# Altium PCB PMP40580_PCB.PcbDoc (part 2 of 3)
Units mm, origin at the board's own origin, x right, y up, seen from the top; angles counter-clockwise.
Board outline 215 x 165 mm, 2 copper layers (Top Layer, Bottom Layer), stack 1.575 mm thick; 235 components, 90 nets, 527 pads, 0 vias.
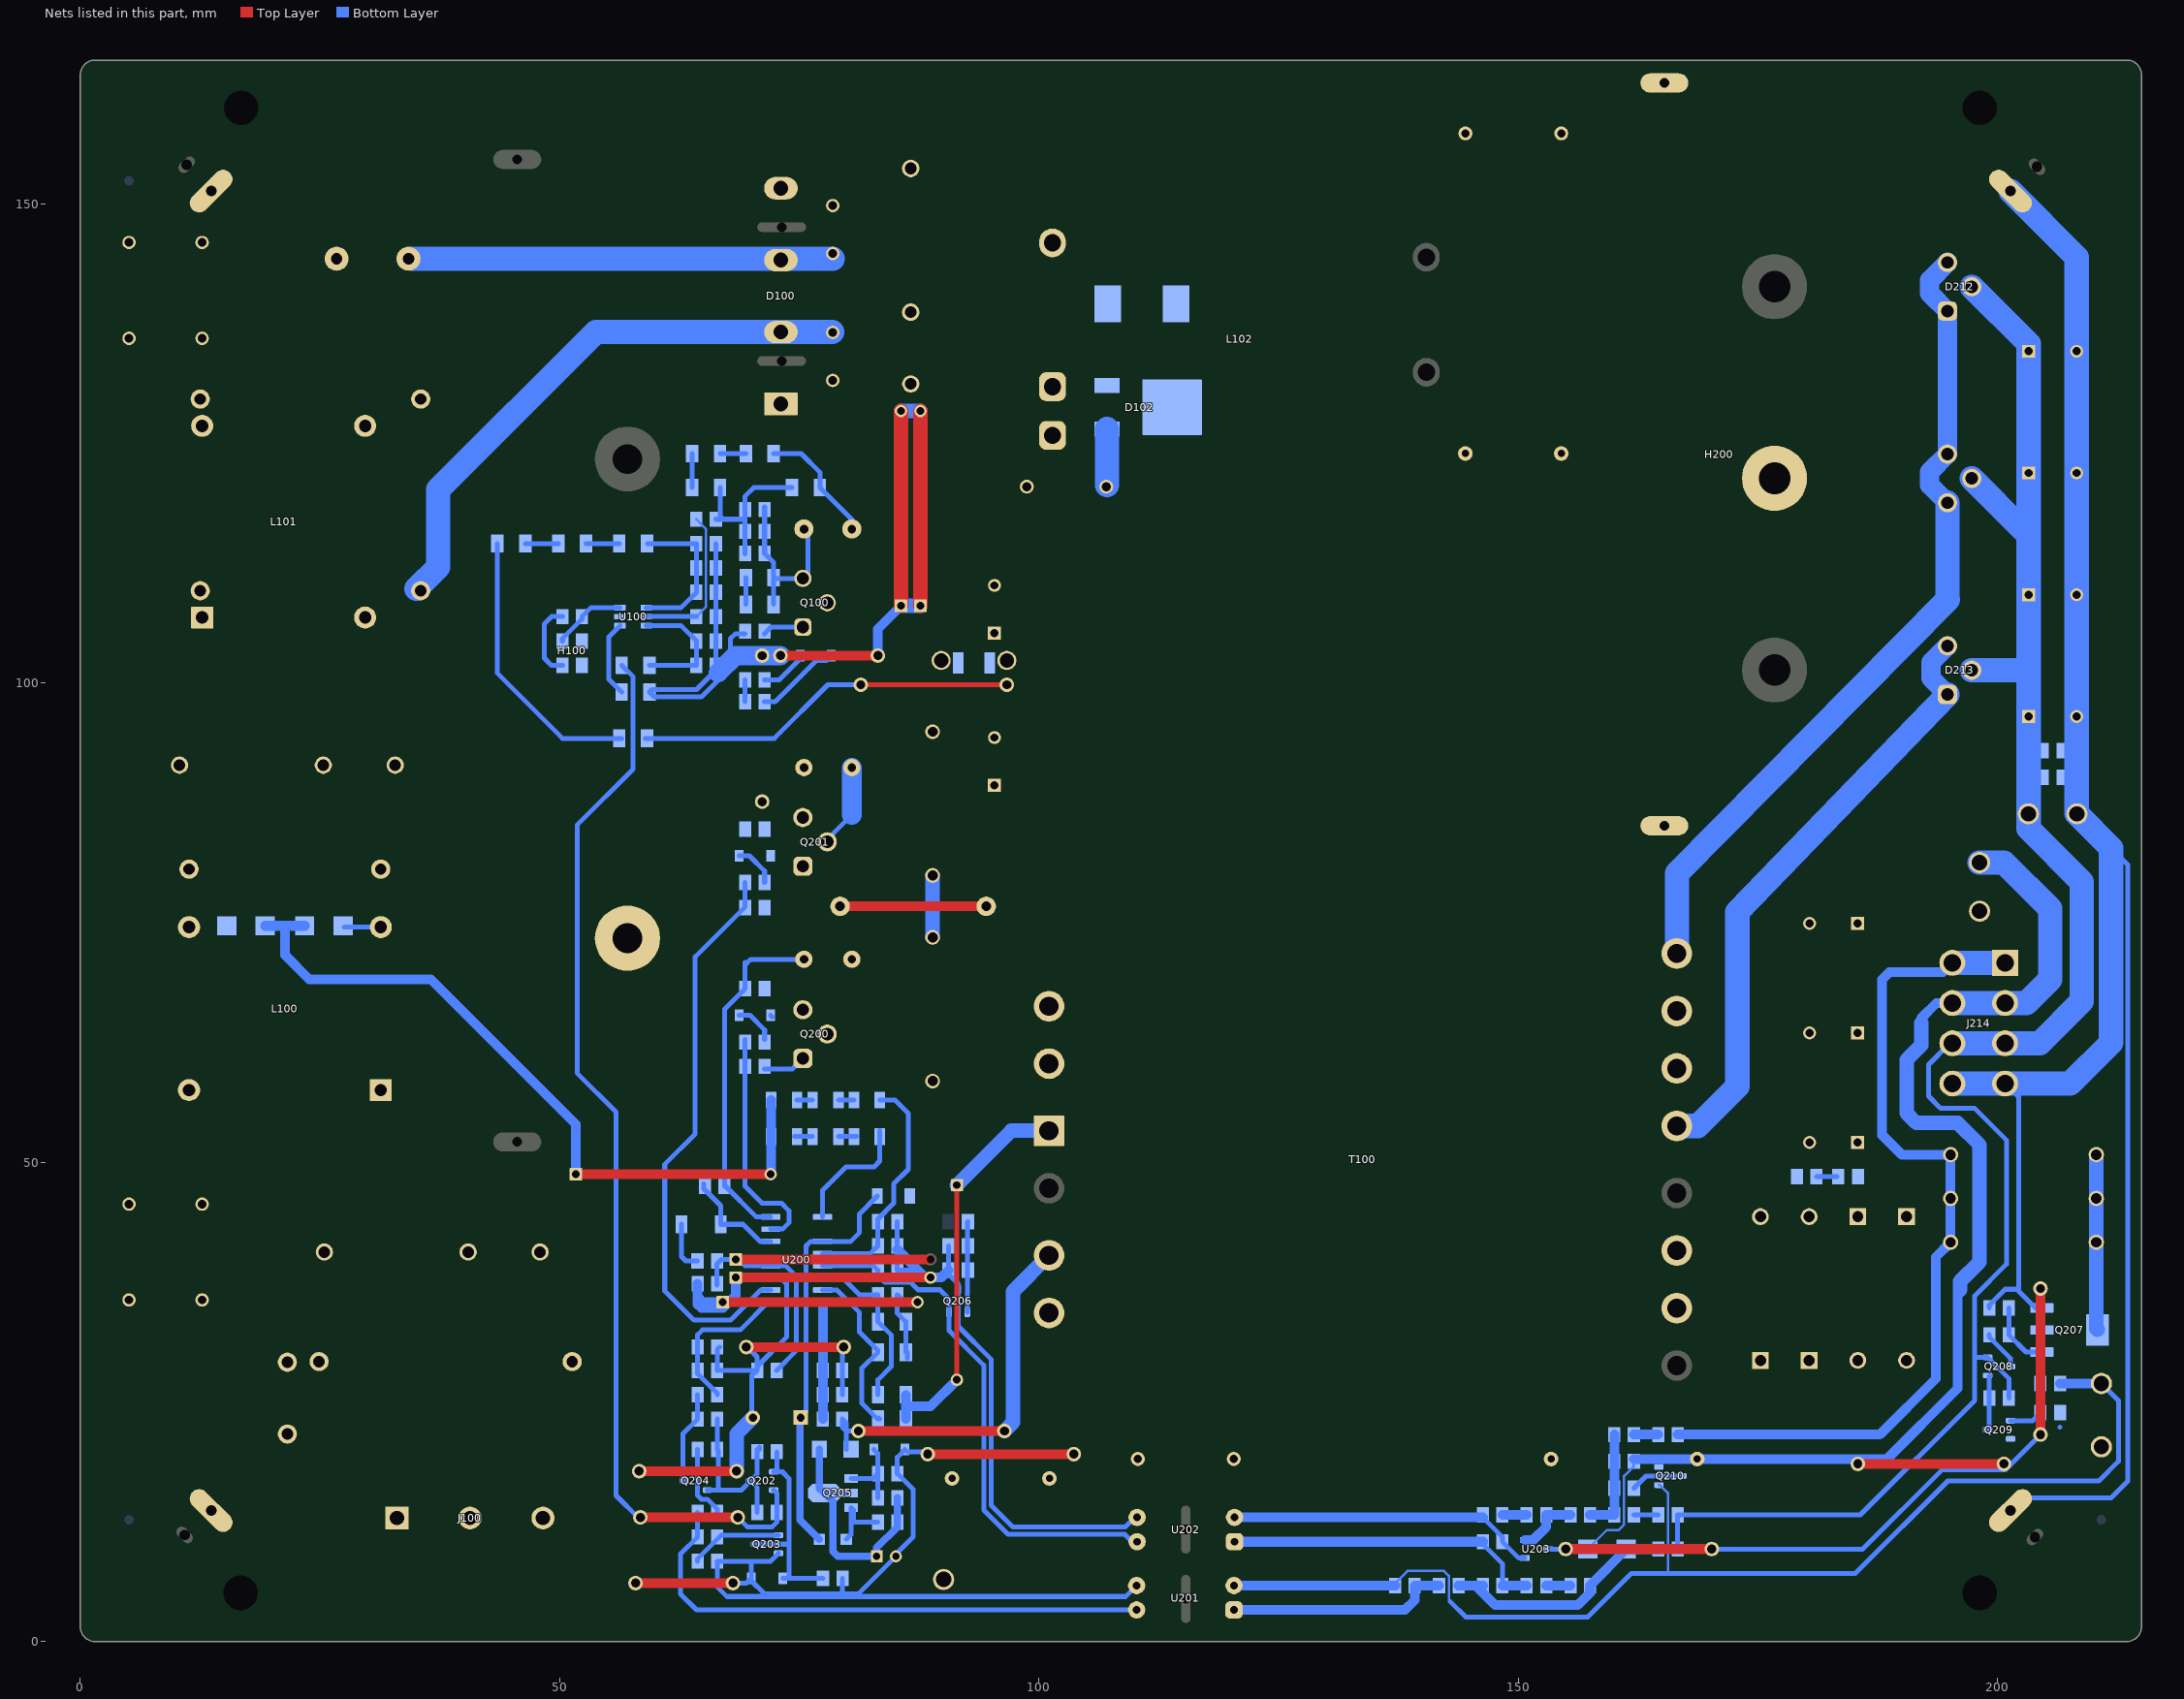
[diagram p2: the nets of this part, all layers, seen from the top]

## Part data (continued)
C217: "CAP, CERM, 10 pF, 50 V,+/- 5%, C0G/NP0, 0805", Cap_Case=0805, Manufacturer=Kemet, Supplier Part Number 1=399-1108-1-ND, TempCo=C0G/NP0, Tolerance_%=5, Value1="0.285 ohm", Value2=50V, ValueDisplayed=10pF
C218: "CAP, CERM, 2.2 µF, 16 V,+/- 10%, X7R, 0805", Cap_Case=0805, Manufacturer=MuRata, TempCo=X7R, Tolerance_%=10, Value2=16V, ValueDisplayed=2.2µF
C219 C221: "CAP, CERM, 470 pF, 25 V,+/- 10%, X7R, 0805", Cap_Case=0805, Manufacturer=MuRata, Supplier Part Number 1=GRM216R71E471KA01D-ND, TempCo=X7R, Tolerance_%=10, Value2=25V, ValueDisplayed=470pF
C220: "CAP, CERM, 0.1 µF, 25 V,+/- 10%, X7R, 0805", Cap_Case=0805, Manufacturer=Kemet, Supplier Part Number 1=399-1168-1-ND, TempCo=X7R, Tolerance_%=10, Value1="0.064 ohm", Value2=25V, ValueDisplayed=0.1µF
C222 C223 C224: "CAP, AL, 6.8 µF, 400 V, +/- 20%, TH", Cap_Case=10x16mm, Manufacturer=Chemi-Con, Supplier Part Number 1=565-1460-ND, Tolerance_%=20, Value2=400V, ValueDisplayed=6.8µF
C225 C226 C227 C228: "CAP, AL, 470 µF, 25 V, +/- 20%, AEC-Q200 Grade 2, TH", Cap_Case=10x16mm, Manufacturer=Chemi-Con, Supplier Part Number 1=565-1958-ND, Tolerance_%=20, Value2=25V, ValueDisplayed=470µF
C229: "CAP, CERM, 10 µF, 25 V,+/- 10%, X7S, 0805", Cap_Case=0805, Manufacturer=MuRata, Supplier Part Number 1=490-10496-1-ND, TempCo=X7S, Tolerance_%=10, Value2=25V, ValueDisplayed=10µF
C230: "CAP, CERM, 0.1 µF, 25 V,+/- 10%, X7R, 0805", Cap_Case=0805, Manufacturer=MuRata, Supplier Part Number 1=490-1673-1-ND, TempCo=X7R, Tolerance_%=10, Value2=25V, ValueDisplayed=0.1µF
C231: "CAP, CERM, 3300 pF, 50 V,+/- 10%, X7R, 0805", Cap_Case=0805, Manufacturer=AVX, Supplier Part Number 1=478-1377-1-ND, TempCo=X7R, Tolerance_%=10, Value1="0.145 ohm", Value2=50V, ValueDisplayed=3300pF
C232: "CAP, CERM, 0.01 µF, 100 V,+/- 10%, X7R, 0805", Cap_Case=0805, Manufacturer=Kemet, Supplier Part Number 1=399-1159-1-ND, TempCo=X7R, Tolerance_%=10, Value1="1.739 ohm", Value2=100V, ValueDisplayed=0.01µF
C233 C234: library part DE1E3KX102MA5BA01, "CAP, CERM, 470 pF, 250 V, +/- 20%, E, Disc, 8x12mm", Cap_Case=DE_800x1200x800, Manufacturer=MuRata, TempCo=E, Tolerance_%=20, Value1=Unknown, Value2=250V, ValueDisplayed=470pF
D100: library part GBU4J-BP, "Diode, P-N-Bridge, 600 V, 15 A, TH", Manufacturer="Taiwan Semiconductor Corporation", Value1=15A, Value2=1V
D101: "Diode, Ultrafast, 600 V, 3 A, SMC", Manufacturer="ON Semiconductor", Supplier Part Number 1=MURS360T3GOSCT-ND, Value1=3A, Value2=1.25V
D102: library part CMP-0077041-3, "Diode, Ultrafast, 600 V, 5 A, DPAK", Manufacturer="ON Semiconductor", Value1=5A, Value2=2.7V
D103 D201 D202: "Diode, Ultrafast, 100 V, 0.15 A, SOD-123", Manufacturer="Diodes Inc.", Supplier Part Number 1=1N4148W-FDICT-ND, Value1=0.15A, Value2=1.25V
D104 D105: "Diode, Ultrafast, 600 V, 1 A, AEC-Q101, SMA", Manufacturer="ON Semiconductor", Supplier Part Number 1=MURA160T3GOSCT-ND, Value1=1A, Value2=1.05V
D203: "Diode, Schottky, 100 V, 2 A, AEC-Q101, SOD-123W", Manufacturer=Nexperia, Supplier Part Number 1=568-12695-1-ND, Value1=2A, Value2=0.83V
D204: "Diode, Zener, 12 V, 500 mW, SOD-123", Manufacturer="ON Semiconductor", Power_W=0.5, Supplier Part Number 1=MMSZ4699T1GOSCT-ND, Value1=0.5W
D205: "Diode, Schottky, 60 V, 1 A, SOD-123F", Manufacturer=Nexperia, Supplier Part Number 1=568-4104-1-ND, Value1=1A, Value2=0.57V
D206: "Diode, Zener, 15 V, 370 mW, AEC-Q101, SOD-123", Manufacturer="Diodes Inc.", Power_W=0.37, Supplier Part Number 1=BZT52C15-FDICT-ND, Value1=0.37W
D207: library part CMP-0029162-1, "Diode, Ultrafast, 600 V, 1 A, AEC-Q101, SMAF", Manufacturer="Fairchild Semiconductor", Supplier Part Number 1=ES1JAFCT-ND, Value1=1A, Value2=1.7V
D208 D209 D210 D211: "Diode, Ultrafast, 200 V, 1.5 A, TH", Manufacturer=STMicroelectronics, Supplier Part Number 1=497-5571-3-ND, Value1=1.5A, Value2=1V
D212 D213: "Diode, Schottky, 45 V, 20 A, TH", Manufacturer=STMicroelectronics, Supplier Part Number 1=497-7567-5-ND, Value1=20A, Value2=0.49V
D214: library part CMP-0005522-2, "Diode, Zener, 11 V, 1.5 W, SMA", Manufacturer="ON Semiconductor", Power_W=1.5W, Supplier Part Number 1=45W9639
F100: "Fuse, 3.15 A, 250 VAC, TH", Irating_A=3.15A, Manufacturer=Littelfuse, Supplier Part Number 1=F3478-ND
FID1 FID2 FID3: library part CMP-0077181-1, "Fiducial mark.  There is nothing to buy or mount.", Manufacturer=N/A
H1 H2 H3 H4: "Standoff, Hex, 1\"L #6-32 Nylon, M-F", Manufacturer=Keystone, Supplier Part Number 1=36-4820-ND
H5 H6 H7 H8: library part CMP-0003679-1, Manufacturer=Keystone, Supplier Part Number 1=36-1903C-ND
H9 H10 H11 H12: library part 108-0740-001, "GND connector"
H13 H14 H15 H16: "MACHINE SCREW PAN PHILLIPS M3 5mm", Manufacturer="B&F Fastener Supply", Supplier Part Number 1=H742-ND
H17 H18 H19: "MACHINE SCREW PAN PHILLIPS M3", Manufacturer="APM HEXSEAL", Supplier Part Number 1=335-1149-ND
H20 H21 H22: "Hex Nuts: M3 X .5MM pitch DIN 934 A2 - 304 Stainless", Manufacturer="InStock Fasteners"
H100: library part HeatSink_2840x500x600_PQFP64-PBH, "Extruded Heatsink, 100mm, CUSTOM", Manufacturer="Texas Instruments"
H200: library part HeatSink_2840x500x600_PQFP64-PBH, "Extruded Heatsink, 75mm, CUSTOM", Manufacturer="Texas Instruments"
J100: library part 691312410003, "Serie 3124 - 7.62mm Open Horizontal PCB Header WR-TBL, 3 pin", Operating Temperature="-40 to 105 degC"
J101 J102 J103 J202 J206 J209 J210: library part CMP-0086939-1, Manufacturer=3M
J104 J106 J201 J203 J204 J211 J212 J213: "Jumper Wire, 600mil spacing, Blue, pkg of 150, TH", Manufacturer=3M, Supplier Part Number 1=923345-06-ND
J105 J200 J205 J207 J208: "Jumper Wire, 400 mil Spacing, Yellow, Pkg of 200", Manufacturer=3M, Supplier Part Number 1=923345-04-ND
J214: "THT Male Header WR-MPC4, Right Angled, Dual Row, pitch 4.2 mm, 8 pins", Contact Resistance="10 mOhm", Operating Temperature="-40 to 105 degC", Working Voltage="600 VAC"
L100 L101: library part "PMP40348 CM", "Coupled inductor, 20 mH, 3 A, 0.16 ohm, TH", Manufacturer=Jewel, ValueDisplayed=20mH
L102: library part BK-35, "Inductor, 200 µH, 0.235 ohm, TH", Manufacturer=Jewel, Value1="0.235 ohm", Value2=A
L103: "Ferrite Bead, 75 ohm @ 100 MHz, 5 A, D3.51xL4.45mm", Manufacturer="Laird-Signal Integrity Products", Supplier Part Number 1=240-2438-1-ND, Value1="0.01 ohm", Value2=5A, ValueDisplayed="75 ohm"
Logo1: library part CMP-0074835-1, "IEC 61010-1 High Voltage Warning"
Logo2: library part CMP-0074837-1, "IEC 61010-1 Hot Surface Warning"
Logo3: library part CMP-0074847-1, "FCC_disclaimer"
Logo4: library part CMP-0074769-1
Q100: "MOSFET, N-CH, 600 V, 18 A, TO-220FP", Alternate Manufacturer=None, Manufacturer=STMicroelectronics, Supplier Part Number 1=497-15115-5-ND, Value1="? ohm", Value2="29 nC"
Q200 Q201: "MOSFET, N-CH, 650 V, 17.5 A, TO-220FP", Alternate Manufacturer=None, Manufacturer="Infineon Technologies", Supplier Part Number 1=IPA65R190CFD-ND, Value1="? ohm", Value2="68 nC"
Q202 Q203 Q209: library part "MMBT3904, Fairchild Semiconductor", "Transistor, NPN, 40 V, 0.2 A, SOT-23", Manufacturer="Fairchild Semiconductor", Supplier Part Number 1=MMBT3904FSCT-ND, Value1="0.2 A", Value2=300
Q204: library part "BC856B-7-F, Diodes Inc.", "Transistor, PNP, 65 V, 0.1 A, SOT-23", Manufacturer="Diodes Inc.", Supplier Part Number 1=BC856B-7FDICT-ND, Value1="0.1 A", Value2=330
Q205: library part "BCX56-16,115, Nexperia", "Transistor, NPN, 80 V, 1 A, AEC-Q101, SOT-89", Manufacturer=Nexperia, Supplier Part Number 1=568-1642-1-ND, Value1="1 A", Value2=250
Q206 Q208: library part "MMBT2907A, Fairchild Semiconductor", "Transistor, PNP, 60 V, 0.8 A, SOT-23", Manufacturer="Fairchild Semiconductor", Supplier Part Number 1=MMBT2907AFSCT-ND, Value1="0.8 A", Value2=300
Q207: "MOSFET, N-CH, 600 V, 0.3 A, SOT-223", Alternate Manufacturer=None, Manufacturer=STMicroelectronics, Supplier Part Number 1=497-3523-1-ND, Value1="? ohm", Value2="4.9 nC"
Q210: "MOSFET, N-CH, 60 V, 0.3 A, SOT-23", Alternate Manufacturer=None, Manufacturer=Vishay-Siliconix, Supplier Part Number 1=2N7002K-T1-E3CT-ND, Value1="4 ohm", Value2="0.4 nC"
R100: "VARISTOR 490V 1.2KA DISC 7MM", Manufacturer=Littelfuse, Supplier Part Number 1=F5397-ND
R102 R103 R104: library part CMP-0016708-3, "RES, 1.65 k, 1%, 0.25 W, AEC-Q200 Grade 0, 1206", Manufacturer=Vishay-Dale, Power_W=250mW, Supplier Part Number 1=541-1.65KFCT-ND, TempCo="100 ppm/C", Tolerance_%=1%, Value2=0.25W, Value_Code=1k65, ValueDisplayed=1.65k
R105: "Thermistor NTC, 4.70 ohm, 20%, 15x7mm", Manufacturer=TDK, Power_W=3.1, Supplier Part Number 1=495-2099-ND, Tolerance_%=20
R106: "RES, 51, 5%, 0.25 W, 1206", Manufacturer=Vishay-Dale, Power_W=0.25, Supplier Part Number 1=541-51ECT-ND, TempCo="200 ppm/C", Tolerance_%=5, Value1=5%, Value2=0.25W, Value_Code=51R0, ValueDisplayed=51
R107 R108 R109 R113 R114 R115: "RES, 3.32 M, 1%, 0.25 W, 1206", Manufacturer=Vishay-Dale, Power_W=0.25, Supplier Part Number 1=541-3.32MFCT-ND, TempCo="100 ppm/C", Tolerance_%=1, Value1=1%, Value2=0.25W, Value_Code=3M32, ValueDisplayed=3.32M
R110: "RES, 110 k, 1%, 0.125 W, 0805", Manufacturer=Vishay-Dale, Power_W=0.125, Supplier Part Number 1=541-110KCCT-ND, TempCo="100 ppm/C", Tolerance_%=1, Value1=1%, Value2=0.125W, Value_Code=110k
R111: "RES, 154 k, 1%, 0.125 W, 0805", Manufacturer=Vishay-Dale, Power_W=0.125, Supplier Part Number 1=541-154KCCT-ND, TempCo="100 ppm/C", Tolerance_%=1, Value1=1%, Value2=0.125W, Value_Code=154k
R112: "RES, 10.0, 1%, 0.25 W, 1206", Manufacturer=Vishay-Dale, Power_W=0.25, Supplier Part Number 1=541-10.0FCT-ND, TempCo="100 ppm/C", Tolerance_%=1, Value1=1%, Value2=0.25W, Value_Code=10R0, ValueDisplayed=10.0
R116: "RES, 24.9 k, 1%, 0.125 W, 0805", Manufacturer=Panasonic, Power_W=0.125, Supplier Part Number 1=P24.9KCCT-ND, TempCo="100 ppm/C", Tolerance_%=1, Value1=1%, Value2=0.125W, Value_Code=24k9, ValueDisplayed=24.9k
R117 R118: "RES, 0.12, 5%, 0.25 W, 1206", Manufacturer=Panasonic, Power_W=0.25, Supplier Part Number 1=P.12PCT-ND, TempCo="250 ppm/C", Tolerance_%=5, Value1=5%, Value2=0.25W, Value_Code=R120, ValueDisplayed=0.12
R119: "RES, 3.0 k, 5%, 0.125 W, 0805", Manufacturer=Vishay-Dale, Power_W=0.125, Supplier Part Number 1=541-3.0KACT-ND, TempCo="200 ppm/C", Tolerance_%=5, Value1=5%, Value2=0.125W, Value_Code=3k00, ValueDisplayed=3.0k
R120: "RES, 270 k, 5%, 0.125 W, 0805", Manufacturer=Vishay-Dale, Power_W=0.125, Supplier Part Number 1=541-270KACT-ND, TempCo="200 ppm/C", Tolerance_%=5, Value1=5%, Value2=0.125W, Value_Code=270k
R121 R200 R203: "RES, 47, 5%, 0.125 W, 0805", Manufacturer=Vishay-Dale, Power_W=0.125, Supplier Part Number 1=541-47ACT-ND, TempCo="200 ppm/C", Tolerance_%=5, Value1=5%, Value2=0.125W, Value_Code=47R0, ValueDisplayed=47
R122 R201 R204 R247: "RES, 22, 5%, 0.125 W, 0805", Manufacturer=Vishay-Dale, Power_W=0.125, Supplier Part Number 1=541-22ACT-ND, TempCo="200 ppm/C", Tolerance_%=5, Value1=5%, Value2=0.125W, Value_Code=22R0, ValueDisplayed=22
R123: "RES, 82.5 k, 1%, 0.125 W, 0805", Manufacturer=Vishay-Dale, Power_W=0.125, Supplier Part Number 1=541-82.5KCCT-ND, TempCo="100 ppm/C", Tolerance_%=1, Value1=1%, Value2=0.125W, Value_Code=82k5, ValueDisplayed=82.5k
R124: "RES, 0, 5%, 0.25 W, 1206", Manufacturer=Vishay-Dale, Power_W=0.25, Supplier Part Number 1=541-0.0ECT-ND, TempCo="200 ppm/C", Tolerance_%=5, Value1=5%, Value2=0.25W, Value_Code=0000, ValueDisplayed=0
R202 R205: "RES, 51 k, 5%, 0.125 W, 0805", Manufacturer=Vishay-Dale, Power_W=0.125, Supplier Part Number 1=541-51KACT-ND, TempCo="200 ppm/C", Tolerance_%=5, Value1=5%, Value2=0.125W, Value_Code=51k0, ValueDisplayed=51k
R207 R213 R215 R234: "RES, 0, 5%, 0.125 W, 0805", Manufacturer=Vishay-Dale, Power_W=0.125, Supplier Part Number 1=541-0.0ACT-ND, TempCo="200 ppm/C", Tolerance_%=5, Value1=5%, Value2=0.125W, Value_Code=0000, ValueDisplayed=0
R208 R214: "RES, 2.0 k, 5%, 0.125 W, 0805", Manufacturer=Vishay-Dale, Power_W=0.125, Supplier Part Number 1=541-2.0KACT-ND, TempCo="200 ppm/C", Tolerance_%=5, Value1=5%, Value2=0.125W, Value_Code=2k00, ValueDisplayed=2.0k
R209 R212 R227 R228 R229 R248 R249: "RES, 10 k, 5%, 0.125 W, 0805", Manufacturer=Vishay-Dale, Power_W=0.125, Supplier Part Number 1=541-10KACT-ND, TempCo="200 ppm/C", Tolerance_%=5, Value1=5%, Value2=0.125W, Value_Code=10k0, ValueDisplayed=10k
R210 R211 R226: "RES, 100 k, 5%, 0.125 W, 0805", Manufacturer=Vishay-Dale, Power_W=0.125, Supplier Part Number 1=541-100KACT-ND, TempCo="200 ppm/C", Tolerance_%=5, Value1=5%, Value2=0.125W, Value_Code=100k
R216: "RES, 866 k, 1%, 0.125 W, 0805", Manufacturer=Vishay-Dale, Power_W=0.125, Supplier Part Number 1=541-866KCCT-ND, TempCo="100 ppm/C", Tolerance_%=1, Value1=1%, Value2=0.125W, Value_Code=866k
R217: "RES, 750 k, 1%, 0.125 W, 0805", Manufacturer=Vishay-Dale, Power_W=0.125, Supplier Part Number 1=541-750KCCT-ND, TempCo="100 ppm/C", Tolerance_%=1, Value1=1%, Value2=0.125W, Value_Code=750k
R218: "RES, 133, 1%, 0.25 W, 1206", Manufacturer=Vishay-Dale, Power_W=0.25, Supplier Part Number 1=541-133FCT-ND, TempCo="100 ppm/C", Tolerance_%=1, Value1=1%, Value2=0.25W, Value_Code=133R, ValueDisplayed=133
R219: "RES, 2.2, 5%, 0.125 W, 0805", Manufacturer=Vishay-Dale, Power_W=0.125, Supplier Part Number 1=541-2.2ACT-ND, TempCo="200 ppm/C", Tolerance_%=5, Value1=5%, Value2=0.125W, Value_Code=2R20, ValueDisplayed=2.2
R220: "RES, 44.2 k, 1%, 0.125 W, 0805", Manufacturer=Vishay-Dale, Power_W=0.125, Supplier Part Number 1=541-44.2KCCT-ND, TempCo="100 ppm/C", Tolerance_%=1, Value1=1%, Value2=0.125W, Value_Code=44k2, ValueDisplayed=44.2k
R221: "RES, 8.06 k, 1%, 0.125 W, 0805", Manufacturer=Vishay-Dale, Power_W=0.125, Supplier Part Number 1=541-8.06KCCT-ND, TempCo="100 ppm/C", Tolerance_%=1, Value1=1%, Value2=0.125W, Value_Code=8k06, ValueDisplayed=8.06k
R222 R223 R224: library part CMP-0017039-3, "RES, 4.99 M, 1%, 0.25 W, AEC-Q200 Grade 0, 1206", Manufacturer=Vishay-Dale, Power_W=250mW, Supplier Part Number 1=541-4.99MFCT-ND, TempCo="100 ppm/C", Tolerance_%=1%, Value2=0.25W, Value_Code=4M99, ValueDisplayed=4.99M
R225: "RES, 300 k, 5%, 0.125 W, 0805", Manufacturer=Vishay-Dale, Power_W=0.125, Supplier Part Number 1=541-300KACT-ND, TempCo="200 ppm/C", Tolerance_%=5, Value1=5%, Value2=0.125W, Value_Code=300k
R230 R235: "RES, 3.01 k, 1%, 0.125 W, 0805", Manufacturer=Vishay-Dale, Power_W=0.125, Supplier Part Number 1=541-3.01KCCT-ND, TempCo="100 ppm/C", Tolerance_%=1, Value1=1%, Value2=0.125W, Value_Code=3k01, ValueDisplayed=3.01k
R231: "RES, 6.04 k, 1%, 0.125 W, 0805", Manufacturer=Vishay-Dale, Power_W=0.125, Supplier Part Number 1=541-6.04KCCT-ND, TempCo="100 ppm/C", Tolerance_%=1, Value1=1%, Value2=0.125W, Value_Code=6k04, ValueDisplayed=6.04k
R232: "RES, 330, 5%, 0.125 W, 0805", Manufacturer=Vishay-Dale, Power_W=0.125, Supplier Part Number 1=541-330ACT-ND, TempCo="200 ppm/C", Tolerance_%=5, Value1=5%, Value2=0.125W, Value_Code=330R, ValueDisplayed=330
R233: "RES, 33.2 k, 1%, 0.125 W, 0805", Manufacturer=Vishay-Dale, Power_W=0.125, Supplier Part Number 1=541-33.2KCCT-ND, TempCo="100 ppm/C", Tolerance_%=1, Value1=1%, Value2=0.125W, Value_Code=33k2, ValueDisplayed=33.2k
R236: "RES, 10, 5%, 0.125 W, 0805", Manufacturer=Vishay-Dale, Power_W=0.125, Supplier Part Number 1=541-10ACT-ND, TempCo="200 ppm/C", Tolerance_%=5, Value1=5%, Value2=0.125W, Value_Code=10R0, ValueDisplayed=10
R237: "RES, 147 k, 1%, 0.125 W, 0805", Manufacturer=Vishay-Dale, Power_W=0.125, Supplier Part Number 1=541-147KCCT-ND, TempCo="100 ppm/C", Tolerance_%=1, Value1=1%, Value2=0.125W, Value_Code=147k
R238 R239: "RES, 499 k, 1%, 0.125 W, 0805", Manufacturer=Vishay-Dale, Power_W=0.125, Supplier Part Number 1=541-499KCCT-ND, TempCo="100 ppm/C", Tolerance_%=1, Value1=1%, Value2=0.125W, Value_Code=499k
R240: "RES, 80.6 k, 1%, 0.125 W, 0805", Manufacturer=Vishay-Dale, Power_W=0.125, Supplier Part Number 1=541-80.6KCCT-ND, TempCo="100 ppm/C", Tolerance_%=1, Value1=1%, Value2=0.125W, Value_Code=80k6, ValueDisplayed=80.6k
R241: "RES, 21.5 k, 1%, 0.125 W, 0805", Manufacturer=Vishay-Dale, Power_W=0.125, Supplier Part Number 1=541-21.5KCCT-ND, TempCo="100 ppm/C", Tolerance_%=1, Value1=1%, Value2=0.125W, Value_Code=21k5, ValueDisplayed=21.5k
R242 R243: "RES, 3.3 M, 5%, 0.125 W, 0805", Manufacturer=Panasonic, Power_W=0.125, Supplier Part Number 1=P3.3MACT-ND, TempCo="150 ppm/C", Tolerance_%=5, Value1=5%, Value2=0.125W, Value_Code=3M30, ValueDisplayed=3.3M
R244 R245 R246: "RES, 100 k, 5%, 2 W, AEC-Q200 Grade 0, Axial resistor", Manufacturer=Vishay-Bccomponents, Power_W=2, Supplier Part Number 1=PPC100KW-2CT-ND, TempCo="250 ppm/C", Tolerance_%=5, Value1=5%, Value2=2W, Value_Code=100k
R250: "RES, 4.7 k, 5%, 0.125 W, 0805", Manufacturer=Vishay-Dale, Power_W=0.125, Supplier Part Number 1=541-4.7KACT-ND, TempCo="200 ppm/C", Tolerance_%=5, Value1=5%, Value2=0.125W, Value_Code=4k70, ValueDisplayed=4.7k
R251: "RES, 20 k, 5%, 0.125 W, 0805", Manufacturer=Vishay-Dale, Power_W=0.125, Supplier Part Number 1=541-20KACT-ND, TempCo="200 ppm/C", Tolerance_%=5, Value1=5%, Value2=0.125W, Value_Code=20k0, ValueDisplayed=20k
T100: library part EE42, "Transformer, 400uH, 14-pin, TH, EE49", Alternate Manufacturer=-, Manufacturer=Jewel
TP200 TP202 TP204 TP206: "Test Point, Multipurpose, Black, TH", Manufacturer=Keystone, Supplier Part Number 1=36-5011-ND
TP201 TP203 TP205: "Test Point, Multipurpose, Red, TH", Manufacturer=Keystone, Supplier Part Number 1=36-5010-ND
U100: "6-Pin Single-Phase Transition-Mode PFC Controller, DBV0006A (SOT-23-6)", Alternate Manufacturer="Texas Instruments"
U200: library part CMP-0077203-3, "Wide Vin LLC Resonant Controller With High-Voltage Start Up Enabling Low Standby Power, DDB0014A (SOIC-14)", Alternate Manufacturer="Texas Instruments", Alternate PartNumber=UCC25640-4DDBT, PartNumber=UCC25640-4DDBR
U201 U202: "Optocoupler, 5.3 kV, 50-600% CTR, TH", Manufacturer=Vishay-Semiconductor, Supplier Part Number 1=VO618A-ND, Voltage_Isolation_Vrms=5300V
U203: "Adjustable Precision Shunt Regulator, 34 ppm / degC, 100 mA, -40 to 85 degC, 3-pin SOT-23 (DBZ), Green (RoHS & no Sb/Br)", Alternate Manufacturer="Texas Instruments", Alternate PartNumber=Equivalent, Rating=Catalog, Supplier Part Number 1=296-17329-2-ND, Temp Coeff(Max)(ppm/ degree C)=92, Temp Coeff(Typ)(ppm/ degree C)=34

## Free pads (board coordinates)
  round 2 hole 1.2: 1(11.336,80.588) 1(12.503,109.634) 1(35.503,109.634) 1(35.503,129.634) 2(31.336,80.588) 3(12.503,129.634)
  round 2 hole 1.5: 1(89.789,102.362) 1(96.647,102.362)
  round 1.524 hole 0.762: 1(90.932,17.018) 1(144.479,123.952) 1(168.656,19.05) 2(101.092,17.018) 2(153.416,19.05) 2(154.479,123.952)
  round 2 hole 1.3: 1(194.767,118.811) 2(197.307,121.351) 3(194.767,123.891)
  round 1.8 hole 1.2: 2(25.34,91.44) 2(40.453,40.64) 2(86.626,138.712)
  oval 5.08x1 hole 1 slot 5.08 at 0 deg unplated: ""(73.152,133.604) ""(73.152,147.574)
  oval 1x5 hole 1 slot 5 at 90 deg unplated: ""(115.316,4.445) ""(115.316,11.684)

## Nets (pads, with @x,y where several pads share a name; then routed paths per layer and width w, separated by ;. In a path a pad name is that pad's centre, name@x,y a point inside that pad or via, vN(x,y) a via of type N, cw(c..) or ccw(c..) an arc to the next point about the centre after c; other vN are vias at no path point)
12V: C225.1 C226.1 C227.1 C228.1 C229.1 C230.1 D212.2 D213.2 J214.3 J214.7 pad.2@197.307,121.351 Q208.2 R235.2 R236.2 R249.2 TP203.1 | length 200
  Bottom Layer w0.508: R235.2@166.624,9.652 R236.2@166.624,13.208 185.674,13.208 197.612,25.146 197.612,29.652 ; J214.7@195.28,62.416 195.004,62.416 192.786,60.198 192.786,56.896 194.056,55.626 197.612,55.626 200.914,52.324 200.914,39.37 197.612,36.068 197.612,29.652 ; R249.2@201.168,25.4 201.168,27.436 Q208.2@198.952,29.652 197.612,29.652
  Bottom Layer w2.54: J214.7@195.28,62.416 J214.3@200.78,62.416 204.402,62.416 208.788,66.802 208.788,79.248 203.24,84.796 C228.1@203.24,96.52 203.24,101.346 ; D213.2@197.307,101.346 203.24,101.346 ; pad.2@197.307,121.351 202.58,116.078 203.24,116.078 ; D212.2@197.307,141.351 203.24,135.418 C225.1@203.24,134.62 C226.1@203.24,121.92 203.24,116.078 ; 203.24,101.346 C227.1@203.24,109.22 203.24,116.078
150V: C222.1 C223.1 C224.1 D208.1 D210.1 J214.1 J214.5 R238.2 R243.2 R244.2 R245.2 R246.2 TP201.1 | length 91.1
  Bottom Layer w1.016: R238.2@166.624,21.59 187.706,21.59 193.548,27.432 193.548,40.112 R246.2@195.092,41.656 R245.2@195.092,46.228 R244.2@195.092,50.8 189.992,50.8 187.96,52.832 187.96,67.31 187.96,69.088 188.722,69.85 194.314,69.85 J214.5@195.28,70.816
  Bottom Layer w2.54: J214.5@195.28,70.816 J214.1@200.78,70.816
ACIN: D104.1 D105.1 J101.1 J101.2 R104.2 R222.2 | length 78
  Top Layer w1.016: J101.1@51.689,48.768 J101.2@72.009,48.768
  Bottom Layer w1.016: D104.1@19.272,74.676 21.336,74.676 ; D105.1@23.4,74.676 21.336,74.676 ; J101.1@51.689,48.768 51.689,53.975 36.576,69.088 23.876,69.088 21.336,71.628 21.336,74.676 ; J101.2@72.009,48.768 J101.2@72.056,48.815 ; J101.2@72.056,48.688 J101.2@72.056,48.815 ; R104.2@72.056,52.435 J101.2@72.056,48.815 ; R104.2@72.056,52.689 R222.2@72.056,56.499
BLK: C220.1 R224.1 R225.2 U200.4 | length 24.8
  Bottom Layer w0.508: U200.4@77.423,40.487 82.397,40.487 C220.1@83.185,41.275 R225.2@83.185,43.815 83.185,44.069 84.836,45.72 84.836,47.752 86.36,49.276 86.36,55.118 84.979,56.499 R224.1@83.392,56.499
BW: C217.1 R220.1 R221.2 U200.8 | length 12
  Bottom Layer w0.508: U200.8@77.423,35.407 U200.8@77.45,35.379
  Bottom Layer w1.016: R220.1@77.45,23.21 C217.1@77.45,28.29 U200.8@77.45,35.179
COMP: C115.1 C116.1 U100.6 | length 7.7
  Bottom Layer w0.508: C116.1@50.292,104.394 50.292,104.648 52.324,106.68 C115.1@52.324,106.934 53.274,107.884 U100.6@56.283,107.884
DRV: R121.1 R122.1 U100.5 | length 2.3
  Bottom Layer w0.508: R121.1@69.342,98.044 R122.1@69.342,100.33
FB: C219.1 Q206.2 U200.5 U202.4 | length 55.8
  Bottom Layer w0.508: U200.5@77.423,39.217 82.703,39.217 C219.1@83.185,38.735 83.185,38.227 83.931,37.481 86.598,37.481 87.376,36.703 89.662,36.703 90.617,35.748 Q206.2@90.617,34.36 90.617,32.446 94.234,28.829 94.234,13.716 96.774,11.176 108.966,11.176 109.728,10.414 U202.4@110.236,10.414
HB: C218.1 D207.1 U200.14 | length 10.9
  Bottom Layer w0.508: C218.1@65.024,47.752 65.024,47.244 66.79,45.478 D207.1@66.79,43.53 69.119,43.53 70.892,41.757 U200.14@72.023,41.757
HO: R200.1 R201.1 U200.15 | length 24.1
  Bottom Layer w0.508: R200.1@69.342,59.754 69.342,47.498 71.12,45.72 73.152,45.72 73.914,44.958 73.914,43.688 73.253,43.027 U200.15@72.023,43.027 ; R200.1@69.342,60.008 R201.1@69.342,62.548 R201.1@69.342,62.802
HS: C201.1 C202.2 C218.2 J201.1 J201.2 Q200.3 Q201.2 R202.1 T100.5 T100.6 U200.16 | length 59.1
  Top Layer w1.016: J201.1@79.248,76.708 J201.2@94.368,76.708
  Bottom Layer w0.508: C218.2@67.198,47.498 67.198,65.991 R202.1@69.342,68.136 69.342,70.866 ; C218.2@67.31,47.498 70.511,44.297 U200.16@72.023,44.297 ; 69.342,70.612 69.914,71.184 C201.1@74.97,71.184 ; Q201.2@78.416,84.18 80.478,86.242
  Bottom Layer w2.032: 80.478,86.242 C202.2@80.478,91.186
HV: R102.1 U200.1 | length 13.2
  Bottom Layer w0.508: U200.1@77.423,44.297 77.423,47.07 79.883,49.53 82.804,49.53 83.392,50.118 R102.1@83.392,52.689 R102.1@83.392,53.324
ISNS: C205.2 C216.1 R218.2 U200.6 | length 18.1
  Bottom Layer w0.508: U200.6@77.423,37.947 79.502,37.947 81.254,36.195 C216.1@83.185,36.195 83.185,33.385 R218.2@83.2,33.37 84.582,31.988 84.582,28.691 83.2,27.309 C205.2@83.2,25.75
Line: F100.2 J100.3
LL: C213.1 R216.1 R217.2 U200.9 | length 16.1
  Bottom Layer w0.508: R216.1@66.421,25.75 66.421,25.908 64.389,27.94 R217.2@64.389,28.29 64.389,32.004 64.897,32.512 68.834,32.512 71.729,35.407 U200.9@72.023,35.407
LO: R203.1 R204.1 U200.10 | length 59.7
  Bottom Layer w0.508: R204.1@69.342,79.185 69.342,76.645 64.135,71.438 64.135,52.959 60.96,49.784 60.96,36.576 64.008,33.528 67.818,33.528 70.967,36.677 U200.10@72.023,36.677
NetC100_1: C100.1 C101.1 F100.1 L100.4 R100.2
NetC103_1: C103.1 C104.2 D104.2 L100.3 L101.4 pad.1@11.336,80.588 pad.3@12.503,129.634
NetC103_2: C103.2 C105.1 D105.2 L100.2 L101.1 pad.1@12.503,109.634 pad.2@25.34,91.44 pad.2@31.336,80.588 | length 2.8
  Bottom Layer w0.508: D105.2@27.536,74.54 L100.2@30.336,74.54
NetC106_2: C106.2 D100.3 R105.2 | length 43.8
  Bottom Layer w2.54: R105.2@34.655,144.272 C106.2@78.486,144.28
NetC107_1: C107.1 D100.2 L101.2 pad.1@35.503,109.634 | length 59.2
  Bottom Layer w2.54: pad.1@35.052,109.855 37.338,112.104 37.338,120.189 53.779,136.63 D100.2@73.076,136.63 C107.1@78.436,136.63
NetC107_2: C107.2 C108.1 D100.1 D101.2 L102.3
NetC111_1: C111.1 C114.2 L102.1 L102.2 L103.1 Q100.2 R113.2 | length 13
  Bottom Layer w0.508: R113.2@72.316,123.952 75.184,123.952 77.178,121.958 C111.1@77.178,120.36 ; C111.1@77.142,120.396 C111.1@77.178,120.36 ; C114.2@80.478,116.078 80.478,117.06 C111.1@77.178,120.36
NetC111_2: C111.2 C112.1 C113.1 R115.1 R116.2 R119.2 | length 21
  Bottom Layer w0.508: R119.2@66.294,117.094 67.056,117.094 ; R115.1@66.728,120.396 66.728,117.422 67.056,117.094 ; R116.2@69.342,113.48 R116.2@69.342,113.538 R116.2@69.342,114.3 ; C112.1@69.342,118.11 C112.1@69.342,118.618 ; C111.2@74.206,120.396 70.231,120.396 69.342,119.507 C112.1@69.342,118.618 ; 67.056,117.094 69.342,117.094 ; R116.2@69.342,114.3 C113.1@69.342,115.824 69.342,117.094 ; R116.2@69.342,114.3 69.342,117.094 ; 69.342,117.094 C112.1@69.342,118.618
NetC112_2: C112.2 C113.2 C114.1 Q100.3 R116.1 R117.2 R118.2 | length 19.3
  Bottom Layer w0.508: C112.2@71.374,118.364 71.374,116.078 R116.1@71.374,113.538 72.316,112.596 R118.2@72.316,110.998 ; R117.2@72.316,108.204 72.316,110.842 72.394,110.92 75.876,110.92 75.876,115.68 C114.1@75.478,116.078
NetC115_2: C115.2 R120.2 | length 8
  Bottom Layer w0.508: R120.2@50.292,101.854 49.137,101.854 48.387,102.604 48.387,106.172 49.149,106.934 C115.2@50.292,106.934
NetC117_1: C117.1 C120.1 R112.1 U100.3 | length 13.3
  Bottom Layer w0.508: U100.3@59.033,105.984 62.672,105.984 C117.1@64.262,104.394 C120.1@64.262,101.854 R112.1@59.362,101.854
NetC203_2: C203.2 C204.1 C205.1 C206.1 J202.1 J202.2 T100.4 | length 47.4
  Top Layer w0.508: J202.2@91.44,27.305 J202.1@91.44,47.625
  Bottom Layer w1.016: C206.1@86.1,23.21 C205.1@86.1,25.704 ; 86.39,24.54 88.675,24.54 J202.2@91.44,27.305
  Bottom Layer w1.524: C203.2@88.9,73.477 C204.1@88.9,79.924 ; J202.1@91.44,47.625 97.107,53.292 T100.4@101.036,53.292
NetC209_1: C209.1 D204.1 Q202.1 Q203.3 R208.1 | length 22.2
  Bottom Layer w0.508: Q203.3@70.428,10.16 73.914,10.16 ; R208.1@72.644,19.812 72.644,18.038 Q202.1@72.32,17.714 73.218,17.714 73.914,17.018 73.914,10.16 ; D204.1@73.265,6.604 C209.1@77.47,6.604 ; 73.914,6.604 73.914,10.16
NetC210_1: C210.1 D206.1 Q205.1 R214.1 | length 8.3
  Bottom Layer w0.508: Q205.1@80.386,16.994 82.653,16.994 C210.1@83.185,17.526 ; D206.1@82.758,20.041 83.185,19.614 C210.1@83.185,17.526 ; R214.1@83.185,14.986 C210.1@83.185,17.526
NetC211_1: C211.1 C212.2 D205.1 U200.3 | length 42.4
  Bottom Layer w0.508: C211.1@75.082,23.47 75.692,24.079 75.692,41.275 76.174,41.757 U200.3@77.423,41.757 80.365,41.757 81.28,42.672 81.28,44.626 C212.2@83.136,46.482
  Bottom Layer w0.762: C211.1@75.082,23.47 75.082,12.672 D205.1@77.086,10.668
NetC221_1: C221.1 Q206.1 R226.2 R227.1 | length 9.5
  Bottom Layer w0.508: Q206.1@92.517,34.36 92.517,43.749 R226.2@92.583,43.815
NetC231_1: C231.1 D214.1 R228.2 R231.2 R235.1 | length 25.3
  Bottom Layer w1.016: R228.2@143.764,5.842 R231.2@146.304,5.842 ; 145.542,5.842 147.574,3.81 156.21,3.81 157.48,5.08 C231.1@157.48,5.842 D214.1@161.258,9.62 ; D214.1@161.258,9.652 D214.1@161.258,9.62 ; R235.1@164.592,9.652 161.29,9.652 D214.1@161.258,9.62
NetC231_2: C231.2 R232.2 | length 2.5
  Bottom Layer w1.016: R232.2@152.908,5.842 C231.2@155.448,5.842
NetC232_1: C232.1 R233.1 | length 2.5
  Bottom Layer w1.016: C232.1@148.336,13.208 R233.1@150.876,13.208
NetC232_2: C232.2 R230.2 U202.2 U203.1 | length 32.4
  Bottom Layer w0.508: C232.2@146.304,12.954 148.336,10.922 R230.2@148.336,10.414 150.048,8.702 U203.1@150.692,8.702
  Bottom Layer w1.016: U202.2@120.396,12.954 C232.2@146.304,12.954
NetD102_1: D102.1 D102.3 L103.2 | length 5.8
  Bottom Layer w2.54: L103.2@107.09,120.677 D102.1@107.09,126.498
NetD103_1: D103.1 R122.2 | length 5
  Bottom Layer w0.508: R122.2@71.374,100.33 72.898,100.33 75.071,102.503 D103.1@75.071,102.87
NetD103_2: D103.2 Q100.1 R121.2 R123.2 | length 13.8
  Bottom Layer w0.508: R121.2@71.374,98.044 72.459,98.044 76.777,102.362 77.837,102.362 D103.2@78.345,102.87 ; R123.2@71.374,105.156 72.058,105.84 Q100.1@75.876,105.84
NetD201_1: D201.1 R201.2 | length 4.3
  Bottom Layer w0.508: D201.1@68.721,65.342 69.85,65.342 71.374,63.818 R201.2@71.374,62.802
NetD201_2: D201.2 Q200.1 R200.2 R202.2 | length 4.7
  Bottom Layer w0.508: R200.2@71.374,59.754 74.282,59.754 Q200.1@75.368,60.84 ; D201.2@71.995,65.342 D201.2@72.182,65.155
NetD202_1: D202.1 R204.2 | length 4.5
  Bottom Layer w0.508: D202.1@68.721,81.979 69.786,81.979 71.374,80.391 R204.2@71.374,79.185
NetD202_2: D202.2 Q201.1 R203.2 R205.2
NetD203_2: D203.2 J203.1 J203.2 R220.2 T100.16 | length 41.5
  Top Layer w1.016: J203.1@81.273,21.971 J203.2@96.393,21.971
  Bottom Layer w0.508: D203.2@79.886,20.066 79.886,21.971 ; J203.1@81.273,21.59 J203.1@81.28,21.59 ; J203.1@81.273,21.971 J203.1@81.153,21.971 79.886,21.971 ; 79.886,21.971 79.482,22.375 R220.2@79.482,23.21 79.886,22.806 79.886,21.971
  Bottom Layer w1.524: J203.2@96.393,21.971 97.282,22.86 97.282,36.538 T100.16@101.036,40.292
NetD205_2: D205.2 Q205.3 R213.1 | length 7.7
  Bottom Layer w0.508: D205.2@79.886,10.668 80.386,11.168 Q205.3@80.386,13.994 80.648,13.732 80.648,12.446 R213.1@83.185,12.446
NetD207_2: D207.2 R219.2 | length 5.2
  Bottom Layer w0.508: D207.2@62.71,43.53 62.71,40.16 63.15,39.72 R219.2@64.369,39.72
NetD208_2: D208.2 D209.1 T100.12
NetD210_2: D210.2 D211.1 T100.13
NetD212_1: D212.1 D212.3 pad.1@194.767,118.811 pad.3@194.767,123.891 T100.7 | length 86.4
  Bottom Layer w2.032: pad.1@194.767,118.811 192.913,120.665 192.913,122.037 pad.3@194.767,123.891 D212.1@194.767,138.811 192.913,140.665 192.913,142.037 D212.3@194.767,143.891
  Bottom Layer w2.54: T100.7@166.536,71.792 166.536,80.176 194.818,108.712 ; 194.767,109.169 pad.1@194.767,118.811
NetD213_1: D213.1 D213.3 T100.10 | length 64.3
  Bottom Layer w2.032: D213.1@194.767,98.806 193.04,100.533 193.04,102.159 D213.3@194.767,103.886
  Bottom Layer w2.54: T100.10@166.536,53.792 168.727,53.792 172.847,57.912 172.847,76.124 D213.1@194.767,98.806
NetL101_3: L101.3 pad.1@35.503,129.634 R105.1
NetQ203_1: Q203.1 R209.1 R210.2 | length 9.7
  Bottom Layer w0.508: R210.2@64.389,8.382 64.389,8.636 66.421,10.668 66.863,11.11 Q203.1@72.828,11.11
NetQ204_1: Q204.1 R211.1 R212.1 | length 8.7
  Bottom Layer w0.508: R211.1@64.389,20.028 64.389,15.24 64.77,14.859 65.405,14.859 66.421,13.843 R212.1@66.421,13.462 ; 64.469,17.714 Q204.1@65.405,17.714
NetQ204_3: Q204.3 R215.1 R216.2 | length 9.8
  Bottom Layer w0.508: Q204.3@63.005,16.764 62.865,16.764 62.865,21.686 R215.1@64.389,23.21 R216.2@64.389,25.75
NetQ207_1: Q207.1 R247.2 R248.2 | length 7
  Bottom Layer w0.508: R248.2@201.168,34.798 R247.2@201.168,32.004 202.96,30.212 Q207.1@204.618,30.212
NetQ207_2: Q207.2 Q207.4 R244.1 R245.1 R246.1 | length 18.3
  Bottom Layer w1.524: R244.1@210.292,50.8 R245.1@210.292,46.228 R246.1@210.292,41.656 210.292,32.638 Q207.4@210.418,32.512
NetQ208_1: Q208.1 Q209.3 R249.1 | length 5.8
  Bottom Layer w0.508: Q209.3@198.952,22.098 199.136,22.282 R249.1@199.136,25.4 199.136,27.682 Q208.1@199.206,27.752
NetQ208_3: Q208.3 R247.1 | length 4.2
  Bottom Layer w0.508: R247.1@199.136,32.004 199.136,31.75 201.352,29.534 Q208.3@201.352,28.702
NetQ209_1: Q209.1 R250.1 R251.2 | length 6.5
  Bottom Layer w0.508: Q209.1@201.352,23.048 203.642,23.048 R251.2@204.47,23.876 R250.1@204.47,26.924
NetQ210_3: Q210.3 R240.1 | length 5.5
  Bottom Layer w0.508: R240.1@162.052,16.002 163.322,17.272 Q210.3@167.062,17.272
NetR102_2: R102.2 R103.1 | length 1.9
  Bottom Layer w0.508: R103.1@79.074,52.689 R102.2@80.946,52.689
NetR103_2: R103.2 R104.1 | length 1.9
  Bottom Layer w0.508: R104.1@74.502,52.689 R103.2@76.374,52.689
NetR106_1: R106.1 R107.2 | length 29.3
  Bottom Layer w0.508: R107.2@43.508,114.554 43.508,101.018 50.292,94.234 R106.1@56.208,94.234 R106.1@56.462,94.234
NetR107_1: R107.1 R108.2 | length 3.5
  Bottom Layer w0.508: R107.1@46.408,114.554 R108.2@49.858,114.554
NetR108_1: R108.1 R109.2 | length 3.5
  Bottom Layer w0.508: R108.1@52.758,114.554 R109.2@56.208,114.554
NetR113_1: R113.1 R114.2 | length 2.7
  Bottom Layer w0.508: R114.2@66.728,123.952 R113.1@69.416,123.952
NetR114_1: R114.1 R115.2 | length 3.6
  Bottom Layer w0.508: R115.2@63.828,120.396 R114.1@63.828,123.952
NetR222_1: R222.1 R223.2 | length 1.6
  Bottom Layer w0.508: R222.1@74.756,56.499 R223.2@76.374,56.499
NetR223_1: R223.1 R224.2 | length 1.6
  Bottom Layer w0.508: R223.1@79.074,56.499 R224.2@80.692,56.499
NetR228_1: R228.1 R229.2 U201.1 | length 23.3
  Bottom Layer w1.016: U201.1@120.342,3.302 138.176,3.302 139.192,4.318 R229.2@139.192,5.842 R228.1@141.732,5.842
NetR230_1: R230.1 R231.1 R232.1 U202.1 | length 33.9
  Bottom Layer w0.508: R230.1@146.304,10.414 146.304,10.16 148.336,8.128 R231.1@148.336,5.842
  Bottom Layer w1.016: U202.1@120.396,10.414 R230.1@146.304,10.414 ; R231.1@148.336,5.842 R232.1@150.876,5.842
NetR233_2: R233.2 R234.1 U203.2 | length 6.6
  Bottom Layer w1.016: U203.2@150.692,10.602 151.572,10.602 152.908,11.938 R233.2@152.908,13.208 R234.1@155.448,13.208
NetR234_2: R234.2 R237.1 R239.1 R240.2 R241.2 | length 10.2
  Bottom Layer w1.016: R234.2@157.48,13.208 R237.1@160.02,13.208 ; R237.1@160.02,13.462 R240.2@160.02,16.002 ; R240.2@160.02,16.256 R241.2@160.02,18.796 ; R241.2@160.02,19.05 R239.1@160.02,21.59
NetR236_1: R236.1 R237.2 | length 2.5
  Bottom Layer w0.508: R237.2@162.052,13.208 R236.1@164.592,13.208
NetR238_1: R238.1 R239.2 | length 2.5
  Bottom Layer w1.016: R239.2@162.052,21.59 R238.1@164.592,21.59
NetR242_2: R242.2 R243.1 | length 2.2
  Bottom Layer w0.508: R242.2@181.102,48.514 R243.1@183.261,48.514
Neutral: C100.2 C102.1 J100.2 L100.1 pad.2@40.453,40.64 R100.1
PE: J100.1
PFC_DC+: C109.1 C110.1 C200.2 C201.2 C203.1 D101.1 D102.2 J104.1 J104.2 pad.1@96.647,102.362 Q200.2 R106.2 | length 40
  Top Layer w0.508: J104.1@81.407,99.822 J104.2@96.647,99.822
  Bottom Layer w0.508: R106.2@58.928,94.234 R106.2@59.108,94.234 72.39,94.234 77.978,99.822 J104.1@81.407,99.822
PFC_VCC: J205.1 J205.2 Q202.2 R112.2 R207.2 | length 113.3
  Top Layer w1.016: J205.1@58.42,12.954 J205.2@68.5,12.954
  Bottom Layer w0.508: R112.2@56.462,101.854 57.658,100.658 57.658,91.023 51.816,85.181 51.816,59.309 55.88,55.245 55.88,15.24 58.166,12.954 J205.1@58.42,12.954 J205.1@58.754,12.954 ; J205.2@68.58,12.954 69.596,11.938 72.136,11.938 72.644,12.446 72.644,15.49 Q202.2@72.32,15.814
PGND: C106.1 C108.2 C109.2 C110.2 C116.2 C117.2 C118.2 C119.2 C120.2 C200.1 C202.1 C204.2 C207.2 C208.2 C209.2 C210.2 C211.2 C212.1 C213.2 C214.2 C215.2 C216.2 C217.2 C219.2 C220.2 C221.2 C233.1 C234.1 D100.4 D204.2 D206.2 H100.2 J102.1 J102.2 J103.1 J103.2 J105.1 J105.2 J106.1 J106.2 J200.1 J200.2 J204.1 J204.2 J207.1 J207.2 J208.1 J208.2 J209.1 J209.2 J210.1 J210.2 pad.1@89.789,102.362 pad.1@90.932,17.018 pad.1@144.479,123.952 pad.2@86.626,138.712 pad.2@101.092,17.018 Q201.3 Q203.2 Q206.3 R110.1 R111.1 R117.1 R118.1 R120.1 R123.1 R124.1 R124.2 R205.1 R210.1 R217.1 R218.1 R221.1 R225.1 R227.2 T100.15 TP200.1 U100.4 U200.11 U201.3 U202.3 | length 418.6
  Top Layer w1.016: J207.1@57.912,6.096 J207.2@67.992,6.096 ; J200.1@58.293,17.78 J200.2@68.373,17.78 ; J209.1@67.169,35.407 J209.2@87.329,35.407 ; J210.1@68.646,37.973 J210.2@88.679,37.973 J210.2@88.806,37.973 ; J208.1@69.549,30.734 J208.2@79.629,30.734 ; J105.2@73.105,102.87 J105.1@83.105,102.87 ; J204.1@88.392,19.558 J204.2@103.632,19.558
  Top Layer w1.524: J102.1@85.598,108.068 J102.2@85.598,128.388 ; J103.1@87.63,108.068 J103.2@87.63,128.388
  Bottom Layer w0.508: U100.4@56.283,105.984 55.118,104.819 55.118,100.404 R124.1@56.462,99.06 ; 64.369,36.342 C214.2@64.369,37.18 ; R110.1@66.294,114.554 R111.1@66.294,112.014 C120.2@66.294,101.854 66.294,101.346 64.262,99.314 59.616,99.314 R124.2@59.362,99.06 59.87,98.552 64.77,98.552 67.818,101.6 67.818,104.648 68.326,105.156 R123.1@69.342,105.156 ; R217.1@66.421,28.29 66.421,30.48 C213.2@66.675,30.734 ; R217.1@66.802,28.29 C215.2@70.592,28.29 ; J207.2@68.072,6.096 69.483,6.096 D204.2@69.991,6.604 ; J210.1@68.672,37.947 U200.11@72.023,37.947 73.051,37.947 73.66,37.338 73.66,31.75 C215.2@70.592,28.682 ; R117.1@69.416,108.204 R118.1@69.416,110.998 ; J208.1@69.549,30.734 70.592,29.691 C215.2@70.592,28.682 ; C211.2@70.055,23.279 70.055,27.753 C215.2@70.592,28.29 ; Q203.2@72.828,9.21 72,8.382 70.104,8.382 ; R221.1@79.482,25.75 C217.2@79.482,28.29 79.482,30.46 J208.2@79.502,30.48 ; C209.2@79.502,6.604 79.502,4.998 ; R225.1@85.217,43.815 C220.2@85.217,41.275 85.217,40.895 C219.2@85.217,38.735 86.995,38.735 ; D206.2@86.033,20.041 85.217,19.224 C210.2@85.217,17.526 86.868,15.875 86.868,10.922 85.074,9.128 C208.2@85.074,8.89 81.182,4.998 79.502,4.998 ; C207.2@86.1,30.195 R218.1@86.1,33.37 85.217,34.253 C216.2@85.217,36.195 86.005,35.407 J209.2@87.169,35.407 ; D206.2@86.262,19.812 J204.1@88.392,19.812 ; C207.2@86.266,29.56 C207.2@86.266,30.195 ; R227.2@90.551,41.275 C221.2@90.551,38.735 90.551,38.354 91.567,37.338 Q206.3@91.567,36.76 91.567,32.893 94.996,29.464 94.996,14.224 97.282,11.938 108.966,11.938 109.982,12.954 U202.3@110.236,12.954 ; U201.3@110.182,5.842 109.039,4.699 67.437,4.699 66.421,5.715 R210.1@66.421,8.382 70.104,8.382 ; D204.2@69.991,6.604 69.991,8.269 70.104,8.382 ; D204.2@69.991,6.604 69.991,6.35 71.343,4.998 79.502,4.998 ; C215.2@70.592,28.29 C215.2@70.592,28.682
  Bottom Layer w1.016: C214.2@64.389,37.338 64.389,35.941 ; J210.1@68.359,37.973 68.359,36.101 67.665,35.407 ; J200.2@68.373,17.78 68.373,21.597 68.453,21.677 ; J105.1@83.185,102.87 83.185,105.655 J102.1@85.598,108.068 ; C220.2@85.217,40.895 88.14,37.973 J210.2@88.679,37.973 89.789,37.973 C221.2@90.551,38.735 ; 64.389,35.941 64.389,35.179 64.77,34.798 67.056,34.798 67.665,35.407 ; 64.389,35.941 64.923,35.407 J209.1@67.009,35.407 67.665,35.407
  Bottom Layer w1.524: J200.2@68.453,17.78 68.453,21.677 C211.2@70.055,23.279 ; J102.1@85.598,108.068 J103.1@87.63,108.068 ; J102.2@85.598,128.388 J103.2@87.63,128.388
  Bottom Layer w2.032: C120.2@66.548,101.092 68.326,102.87 J106.2@71.12,102.87 J105.2@73.025,102.87
PS_ON: Q210.1 R229.1 R250.2 TP205.1 U201.2 | length 126.1
  Bottom Layer w0.254: R229.1@137.16,5.842 137.16,6.096 138.43,7.366 142.24,7.366 142.748,6.858 142.748,4.318 142.875,4.191 ; Q210.1@164.662,16.322 164.78,16.322 165.608,15.494 165.608,7.112
  Bottom Layer w0.508: 142.875,4.191 144.526,2.54 157.226,2.54 161.798,7.112 165.608,7.112 185.166,7.112 194.818,16.764 210.566,16.764 212.598,18.796 212.598,25.146 TP205.1@210.82,26.924
  Bottom Layer w1.016: U201.2@120.342,5.842 R229.1@137.16,5.842 ; R250.2@206.502,26.924 TP205.1@210.82,26.924
RVCC: J206.2 R226.1 | length 5.5
  Bottom Layer w0.508: J206.2@88.679,39.878 88.679,43.213 89.281,43.815 R226.1@90.551,43.815
RVCC: C214.1 C215.1 J206.1 Q202.3 Q204.2 R207.1 R208.2 R211.2 R215.2 R219.1 U200.12 | length 62.5
  Top Layer w1.016: J206.1@68.486,39.878 88.646,39.878
  Bottom Layer w0.508: Q204.2@65.405,15.814 66.548,15.814 ; C214.1@66.401,37.18 C214.1@66.401,37.358 ; R215.2@66.421,23.21 R211.2@66.421,20.028 66.548,19.901 66.548,15.814 ; C214.1@66.421,37.338 C214.1@66.401,37.358 ; R207.1@70.612,13.462 70.612,16.072 Q202.3@69.92,16.764 ; R208.2@70.612,20.028 70.866,20.282 70.866,20.066 R208.2@70.612,19.812 70.612,17.456 Q202.3@69.92,16.764 ; C215.1@72.624,28.29 74.676,30.342 74.676,38.1 73.559,39.217 U200.12@72.023,39.217 69.307,39.217 68.646,39.878 66.909,39.878 66.401,39.37 C214.1@66.401,37.358 ; 66.548,15.814 68.97,15.814 Q202.3@69.92,16.764
SGND: C101.2 C102.2 C104.1 C105.2 C222.2 C223.2 C224.2 C225.2 C226.2 C227.2 C228.2 C229.2 C230.2 C233.2 C234.2 D209.2 D211.2 D214.2 H9.1 H10.1 H11.1 H12.1 H200.1 H200.2 J211.1 J211.2 J212.1 J212.2 J213.1 J213.2 J214.2 J214.4 J214.6 J214.8 pad.1@168.656,19.05 pad.2@153.416,19.05 pad.2@154.479,123.952 Q207.3 Q209.2 Q210.2 R241.1 R242.1 R248.1 R251.1 T100.8 T100.9 TP202.1 TP204.1 TP206.1 U203.3 | length 436.5
  Top Layer w1.016: J213.2@154.94,9.652 J213.1@170.18,9.652 ; J212.1@185.42,18.542 J212.2@200.66,18.542 ; J211.1@204.47,21.59 J211.2@204.47,36.83
  Bottom Layer w0.254: D214.2@157.004,9.652 D214.2@157.258,9.652 159.246,11.64 160.484,11.64 161.036,12.192 161.036,17.272 162.052,18.288 R241.1@162.052,18.796
  Bottom Layer w0.508: U203.3@153.092,9.652 J213.2@154.94,9.652 D214.2@157.004,9.652 ; J213.1@170.434,9.652 185.928,9.652 194.183,17.907 200.787,17.907 J211.1@204.47,21.59 ; R248.1@199.136,34.798 199.136,35.109 200.78,36.753 202.007,36.753 ; J214.4@200.78,58.216 202.184,56.812 202.184,36.753 202.007,36.753 ; H10.1@201.344,13.667 202.663,14.986 211.836,14.986 213.56,16.71 213.56,81.08 211.836,82.804 ; Q207.3@204.618,34.812 203.948,34.812 202.007,36.753
  Bottom Layer w1.016: R241.1@162.052,19.05 pad.1@168.656,19.05 188.468,19.05 195.834,26.416 195.834,36.703 ; 192.024,64.516 192.024,65.024 193.616,66.616 J214.6@195.28,66.616
  Bottom Layer w1.524: 192.024,64.516 192.024,62.23 190.5,60.706 190.5,55.118 191.516,54.102 195.834,54.102 198.12,51.816 198.12,39.624 196.088,37.592 196.088,36.703
  Bottom Layer w2.54: J214.8@195.28,58.216 J214.4@200.78,58.216 207.568,58.216 211.836,62.484 211.836,82.804 TP202.1@208.28,86.36 208.24,86.4 C228.2@208.24,96.52 C227.2@208.24,109.22 C226.2@208.24,121.92 C225.2@208.24,134.62 208.24,144.436 H12.1@201.344,151.332 ; J214.6@195.28,66.616 203.014,66.616 205.486,69.088 205.486,76.454 200.66,81.28 TP204.1@198.12,81.28
STBY: R209.2 R212.2 U201.4 | length 57.5
  Bottom Layer w0.508: R212.2@64.389,13.462 R209.2@64.389,10.922 62.611,9.144 62.611,4.953 64.262,3.302 U201.4@110.182,3.302
VCC: C208.1 D203.1 Q205.2 Q205.4 R213.2 R214.2 | length 25.6
  Bottom Layer w0.508: Q205.4@77.586,15.494 Q205.2@80.186,15.494
  Bottom Layer w0.762: D203.1@77.086,20.066 77.086,15.994 Q205.4@77.586,15.494 78.486,14.594 78.486,9.398 78.994,8.89 C208.1@83.074,8.89 83.074,9.795 85.217,11.938 R213.2@85.217,12.446 R214.2@85.217,14.986
VCR: C206.2 C207.1 U200.7 | length 18.2
  Bottom Layer w0.508: U200.7@77.423,36.677 78.92,36.677 81.28,34.317 81.28,32.281 83.2,30.361 C207.1@83.2,30.195 81.534,28.529 81.534,24.84 C206.2@83.164,23.21 ; C206.2@83.265,23.311 C206.2@83.366,23.21
VOSNS: C119.1 R109.1 R110.2 R111.2 U100.1 | length 16.1
  Bottom Layer w0.508: U100.1@59.033,107.884 62.672,107.884 C119.1@64.262,109.474 R111.2@64.262,112.014 R110.2@64.262,114.554 R109.1@59.144,114.554
ZCD: C118.1 R119.1 U100.2 | length 16.2
  Bottom Layer w0.254: C118.1@64.262,106.934 65.278,107.95 65.278,116.078 R119.1@64.262,117.094
  Bottom Layer w0.508: U100.2@59.033,106.934 C118.1@64.262,106.934
pads on no net: FID1.1 FID2.1 FID3.1 H1.0 H1.MH H2.0 H2.MH H3.0 H3.MH H4.0 H4.MH H5.0 H6.0 H7.0 H8.0 H9.2 H10.2 H11.2 H12.2 H13.0 H14.0 H15.0 H16.0 H100. H100.1 H200. L102.4 L102.6 T100.11 T100.14 T100.17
